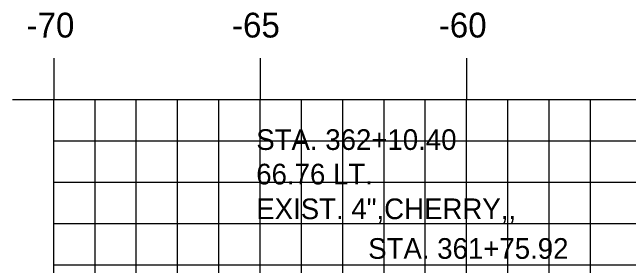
# Model space of a CAD drawing. Extents: x 1146746 to 1146916, y 608981 to 609091.
# Drawn here: x 1146758.43 to 1146773.35, y 609006.32 to 609012.44 of the extents above; entities that cross this region are included whole.
import ezdxf

# ---------------------------------------------------------------- set-up
doc = ezdxf.new("R2010")
doc.units = 0
for name, color, linetype in [('D_Text_Monospaced', 7, 'Continuous'), ('H_V ANNOTATION', 7, 'Continuous'), ('MAJOR', 7, 'Continuous'), ('MINOR', 7, 'Continuous')]:
    doc.layers.add(name, color=color, linetype=linetype)

msp = doc.modelspace()

# ---------------------------------------------------------------- linework, layer by layer
at = {"layer": 'MAJOR'}
for p, q in [((1146759.428, 609011.337), (1146759.428, 609010.335)), ((1146764.428, 609011.337), (1146764.428, 609010.335)), ((1146769.428, 609011.337), (1146769.428, 609010.335)), ((1146758.426, 609010.335), (1146759.428, 609010.335)), ((1146759.428, 609010.335), (1146899.428, 609010.335)), ((1146759.428, 608990.335), (1146759.428, 609010.335)), ((1146759.428, 608990.335), (1146759.428, 609010.335)), ((1146759.428, 609010.335), (1146899.428, 609010.335)), ((1146764.428, 608990.335), (1146764.428, 609010.335)), ((1146769.428, 608990.335), (1146769.428, 609010.335))]:
    msp.add_line(p, q, dxfattribs=at)
at = {"layer": 'MINOR'}
for p, q in [((1146759.428, 608990.335), (1146759.428, 609010.335)), ((1146760.428, 608990.335), (1146760.428, 609010.335)), ((1146761.428, 608990.335), (1146761.428, 609010.335)), ((1146762.428, 608990.335), (1146762.428, 609010.335)), ((1146763.428, 608990.335), (1146763.428, 609010.335)), ((1146765.428, 608990.335), (1146765.428, 609010.335)), ((1146766.428, 608990.335), (1146766.428, 609010.335)), ((1146767.428, 608990.335), (1146767.428, 609010.335)), ((1146768.428, 608990.335), (1146768.428, 609010.335)), ((1146770.428, 608990.335), (1146770.428, 609010.335)), ((1146771.428, 608990.335), (1146771.428, 609010.335)), ((1146772.428, 608990.335), (1146772.428, 609010.335)), ((1146759.428, 609009.335), (1146899.428, 609009.335)), ((1146759.428, 609009.335), (1146760.43, 609009.335)), ((1146759.428, 609008.335), (1146899.428, 609008.335)), ((1146759.428, 609008.335), (1146760.43, 609008.335)), ((1146759.428, 609007.335), (1146899.428, 609007.335)), ((1146759.428, 609007.335), (1146760.43, 609007.335)), ((1146759.428, 609006.335), (1146899.428, 609006.335)), ((1146759.428, 609006.335), (1146760.43, 609006.335))]:
    msp.add_line(p, q, dxfattribs=at)

# ---------------------------------------------------------------- texts
at = {"layer": 'D_Text_Monospaced'}
for s, height, p in [('STA. 362+10.40', 0.49998, (1146764.333, 609009.116)), ('66.76 LT.', 0.5, (1146764.333, 609008.282)), ('EXIST. 4",CHERRY,,', 0.49998, (1146764.333, 609007.442)), ('STA. 361+75.92', 0.49998, (1146767.044, 609006.483))]:
    msp.add_text(s, height=height, dxfattribs=at).set_placement(p)
at = {"layer": 'H_V ANNOTATION'}
for s, p in [('-70', (1146758.769, 609011.835)), ('-65', (1146763.745, 609011.835)), ('-60', (1146768.753, 609011.835))]:
    msp.add_text(s, height=0.6, dxfattribs=at).set_placement(p)

doc.saveas('drawing.dxf')
